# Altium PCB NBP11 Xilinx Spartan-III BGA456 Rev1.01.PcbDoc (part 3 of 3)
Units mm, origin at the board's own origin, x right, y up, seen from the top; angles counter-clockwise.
Board outline 69 x 80.99 mm, 6 copper layers (Top Layer, MidLayer1, InternalPlane1, InternalPlane2, MidLayer2, Bottom Layer); 105 components, 277 nets, 967 pads, 559 vias.
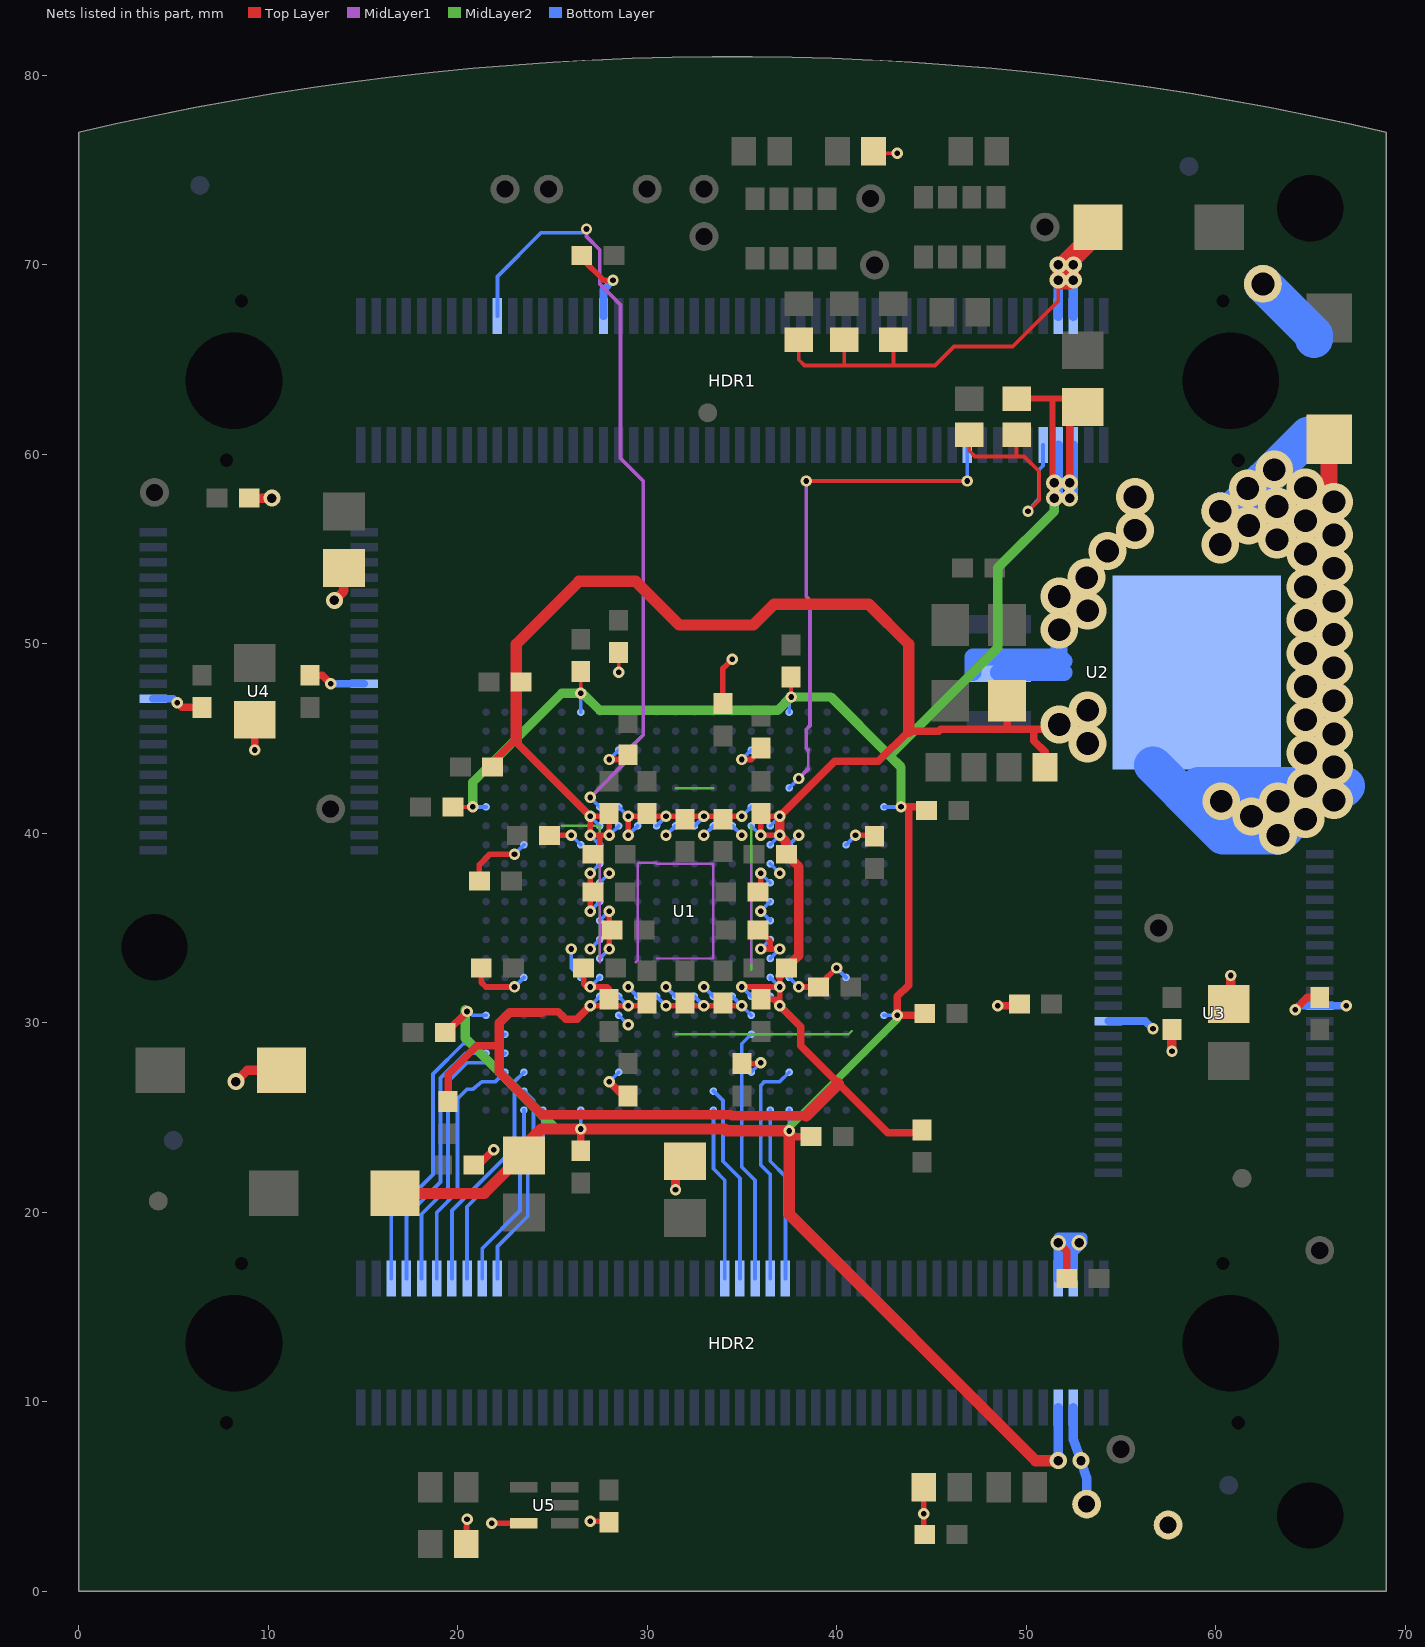
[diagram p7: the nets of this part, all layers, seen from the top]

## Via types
v1: diameter 0.6, hole 0.3, Top Layer to Bottom Layer, tented both sides, 480 vias
v2: diameter 2, hole 1.2, Top Layer to Bottom Layer, tented both sides, 42 vias
v3: diameter 0.9, hole 0.5, Top Layer to Bottom Layer, tented both sides, 33 vias
v4: diameter 0.8, hole 0.5, Top Layer to Bottom Layer, tented both sides, 2 vias
v5: diameter 1.3, hole 0.9, Top Layer to Bottom Layer, tented both sides, 1 vias
v6: diameter 1.8, hole 0.9, Top Layer to Bottom Layer, tented both sides, 1 vias

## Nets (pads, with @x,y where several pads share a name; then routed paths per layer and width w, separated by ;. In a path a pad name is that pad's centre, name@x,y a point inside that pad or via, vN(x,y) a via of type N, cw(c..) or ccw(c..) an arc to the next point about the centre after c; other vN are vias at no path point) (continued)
SW3: HDR2.50 U1.N22 | length 9.1
  Bottom Layer w0.2: U1.N22@33.5,25.4 33.5,22.3 34.1,21.7 HDR2.50@34.1,16.5
SW4: HDR2.52 U1.N21 | length 10.5
  Bottom Layer w0.2: U1.N21@33.5,26.4 34,25.9 34,22.7 34.9,21.8 HDR2.52@34.9,16.5
SW5: HDR2.54 U1.R18 | length 13.4
  Bottom Layer w0.2: U1.R18@35.5,29.4 35,28.9 35,22.4 35.7,21.7 HDR2.54@35.7,16.5
SW6: HDR2.56 U1.U20 | length 12.2
  Bottom Layer w0.2: HDR2.56@36.5,16.5 36.5,22 36,22.5 36,26.7 36.2,26.9 37,26.9 U1.U20@37.5,27.4
SW7: HDR2.58 U1.T22 | length 9.2
  Bottom Layer w0.2: U1.T22@36.5,25.4 36.5,22.7 37.3,21.9 HDR2.58@37.3,16.5
SWC0: HDR2.18 U1.C21 | length 11.2
  Bottom Layer w0.2: HDR2.18@21.3,16.5 21.3,18.1 23.3,20.1 23.3,22.5 24,23.2 24,25.9 U1.C21@23.5,26.4
SWC1: HDR2.16 U1.C22 | length 10.1
  Bottom Layer w0.2: HDR2.16@20.5,16.5 20.5,20.3 23.5,23.3 U1.C22@23.5,25.4
SWC2: HDR2.14 U1.C20 | length 12.5
  Bottom Layer w0.2: HDR2.14@19.7,16.5 19.7,18.1 19.7,20.1 23,23.4 23,26.9 U1.C20@23.5,27.4
SWC3: HDR2.6 U1.B18 | length 16.4
  Bottom Layer w0.2: HDR2.6@16.5,16.5 16.5,19.8 18.7,22 18.7,27.3 20.3,28.9 22,28.9 U1.B18@22.5,29.4
SWR0: HDR2.20 U1.D22 | length 9.9
  Bottom Layer w0.2: HDR2.20@22.1,16.5 22.1,18.2 23.7,19.8 23.7,22.3 24.5,23.1 U1.D22@24.5,25.4
SWR1: HDR2.12 U1.B20 | length 13
  Bottom Layer w0.2: HDR2.12@18.9,16.5 18.9,20 20,21.1 20,26 20.5,26.5 20.8,26.5 21.3,26.9 22,26.9 U1.B20@22.5,27.4
SWR2: HDR2.10 U1.B19 | length 14.6
  Bottom Layer w0.2: HDR2.10@18.1,16.5 18.1,19.9 19.5,21.3 19.5,26.9 20.5,27.9 22,27.9 U1.B19@22.5,28.4
SWR3: HDR2.8 U1.A19 | length 14.3
  Bottom Layer w0.2: HDR2.8@17.3,16.5 17.3,19.8 19.1,21.6 19.1,27.1 20.4,28.4 U1.A19@21.5,28.4
TEST: HDR1.81 U1.U5 | length 27.2
  Top Layer w0.2: v1(38.4,58.6) v1(46.9,58.6)
  MidLayer1 w0.127: 38.5,43.4 38.5,44.4
  MidLayer1 w0.2: v1(38,42.9) 38.5,43.4 ; v1(38.4,58.6) 38.4,52.5 38.6,52.3 38.6,45.7 38.4,45.5 38.4,44.5 38.5,44.4
  Bottom Layer w0.2: U1.U5@37.5,42.4 v1(38,42.9) ; v1(46.9,58.6) HDR1.81@46.9,60.5
VCC: C2.1 C3.1 C9.1 C10.1 C11.1 C12.1 C13.1 C14.1 C15.1 C16.1 C18.2 C35.1 C36.1 C37.1 C38.1 C39.1 C40.1 C41.1 C42.1 C43.1 C44.1 C45.1 C46.1 C47.1 C48.1 C49.1 C50.1 C51.1 C52.1 C53.1 C54.1 C55.1 C56.1 C61.1 C62.1 C63.1 C64.1 HDR1.34 HDR1.94 HDR1.96 HDR2.94 HDR2.96 R1.2 R2.2 R3.2 R4.1 R12.1 R13.2 TP3.1 U1.C8 U1.C15 U1.F8 U1.F15 U1.G9 U1.G10 U1.G11 U1.G12 U1.G13 U1.G14 U1.H3 U1.H6 U1.H17 U1.H20 U1.J7 U1.J16 U1.K7 U1.K16 U1.L7 U1.L16 U1.M7 U1.M16 U1.N7 U1.N16 U1.P7 U1.P16 U1.R3 U1.R6 U1.R17 U1.R20 U1.T9 U1.T10 U1.T11 U1.T12 U1.T13 U1.T14 U1.U8 U1.U15 U1.Y8 U1.Y15 U3.11 U3.33 U4.11 U4.33 U5.5 | length 151.2
  Top Layer w0.2: v1(28.5,48.5) C50.1@28.5,49.55 ; R2.2@38,66.05 38,65 38.3,64.7 40.4,64.7 ; R3.2@40.4,66.05 40.4,64.7 ; R1.2@41.95,76 42.3,75.9 v1(43.2,75.9) ; R4.1@43,66.05 43,64.7 ; v3(51.7,70) v3(51.7,69.2) 51.7,69 51.7,68.1 49.3,65.7 46.2,65.7 45.2,64.7 43,64.7 ; 40.4,64.7 43,64.7
  Top Layer w0.3: R13.2@20.425,2.501 v1(20.5,3.8) ; R13.2@20.45,2.5 R13.2@20.7,2.5 ; C54.1@21.15,37.5 21.15,38.35 21.7,38.9 v1(23,38.9) ; C10.1@21.25,32.9 21.25,32.15 21.5,31.9 v1(23,31.9) ; v1(21.8,3.6) U5.5@23.5,3.6 ; C51.1@24.85,39.9 v1(26,39.9) ; C38.1@26.55,70.498 26.55,70.35 27.7,69.2 v1(28.2,69.2) ; v1(27,3.7) C48.1@28,3.7 ; v1(27,35.9) 27,36.9 v1(27,37.9) ; v1(28,33.9) 28,34.9 v1(28,35.9) ; v1(28,43.9) C15.1@28.9,43.9 ; v1(29,39.9) v1(29,40.9) 30,40.9 v1(31,40.9) 32,40.9 v1(33,40.9) 34,40.9 v1(35,40.9) ; v1(31,30.9) 32,30.9 v1(33,30.9) 34,30.9 v1(35,30.9) ; C9.1@34,46.85 34,48.7 v1(34.5,49.2) ; C49.1@35,27.85 35.95,27.85 v1(36,27.9) ; v1(35,43.9) 35.5,43.9 36,44.4 C11.1@36,44.5 ; C44.1@35.85,34.9 35.9,34.9 36.5,34.3 36.5,33.9 ; C45.1@35.85,36.9 36,37.05 v1(36,37.9) ; v1(36,33.9) 36.5,33.9 ; v1(37,33.9) 36.5,33.9 ; v1(38,31.9) C53.1@39.05,31.9 39.05,31.95 v1(40,32.9) ; v1(41,39.9) C52.1@41.95,39.9 ; C36.1@44.6,3.05 v1(44.6,4.1) R12.1@44.6,5.5
  Top Layer w0.4: v1(5.2,46.9) 5.45,46.65 C35.1@6.5,46.65 ; v1(9.3,44.4) C64.1@9.3,46 ; C12.1@12.2,48.35 12.85,48.35 v1(13.3,47.9) ; C55.1@20.85,22.5 21.1,22.5 v1(21.9,23.3) ; v1(28,26.9) 28.8,26.1 C18.2@29,26.1 ; v1(48.5,30.9) C13.1@49.6,30.9 ; v4(51.7,18.4) 52.15,17.95 C37.1@52.15,16.5 ; v1(64.2,30.7) 64.85,31.35 C47.1@65.5,31.35
  Top Layer w0.5: v3(8.3,26.9) 8.9,27.5 C3.1@10.7,27.5 10.7,27 C3.1@10.8,27 ; C39.1@9.1,57.7 v3(10.2,57.7) ; v3(13.5,52.3) 14,52.8 C61.1@14,54 ; 31.5,21.5 31.5,22.7 C62.1@31.5,22.9 ; v1(57.7,28.5) C46.1@57.7,29.65 ; C63.1@60.8,31 v1(60.8,32.5)
  Top Layer w0.6: v3@52.2,70.1 52.1,70 52.1,69.2 v3@52.1,69 ; C2.1@53.8,71.4 52.5,70.1 v3(52.5,70) v3(52.5,69.2) 52.3,69 v3@52.1,69 ; C2.1@53.8,72 53.7,72 52.1,70.4 v3(51.7,70) v3(51.7,69.2) 51.7,69 v3@52.1,69
  Bottom Layer w0.2: v1(23,31.9) U1.C15@23.5,32.4 ; v1(23,38.9) U1.C8@23.5,39.4 ; v1(26,33.9) 26,32.9 U1.F15@26.5,32.4 ; v1(26,39.9) U1.F8@26.5,39.4 ; v1(27,33.9) U1.G13@27.5,34.4 ; v1(27,35.9) U1.G11@27.5,36.4 ; v1(27,37.9) U1.G9@27.5,38.4 ; U1.G14@27.5,33.4 27.55,33.45 v1(28,33.9) ; U1.G12@27.5,35.4 v1(28,35.9) ; U1.G10@27.5,37.4 v1(28,37.9) ; v1(28,26.9) U1.H20@28.5,27.4 ; v1(28,43.9) U1.H3@28.5,44.4 ; U1.H17@28.5,30.4 v1(29,29.9) ; U1.H6@28.5,41.4 v1(29,40.9) ; v1(29,31.9) U1.J16@29.5,31.4 ; v1(29,39.9) U1.J7@29.5,40.4 ; U1.K16@30.5,31.4 v1(31,30.9) ; U1.K7@30.5,40.4 30.55,40.45 v1(31,40.9) ; v1(31,31.9) U1.L16@31.5,31.4 ; v1(31,39.9) U1.L7@31.5,40.4 ; U1.M16@32.5,31.4 v1(33,30.9) ; U1.M7@32.5,40.4 v1(33,40.9) ; v1(33,31.9) 33.45,31.45 U1.N16@33.5,31.4 ; v1(33,39.9) U1.N7@33.5,40.4 ; U1.P16@34.5,31.4 v1(35,30.9) U1.R17@35.5,30.4 ; U1.P7@34.5,40.4 v1(35,39.9) ; v1(35,40.9) U1.R6@35.5,41.4 ; v1(35,43.9) U1.R3@35.5,44.4 ; U1.R20@35.5,27.4 35.55,27.45 v1(36,27.9) ; v1(36,33.9) U1.T13@36.5,34.4 ; v1(36,37.9) U1.T10@36.5,37.4 ; U1.T14@36.5,33.4 v1(37,33.9) ; U1.T12@36.5,35.5 U1.T12@36.5,35.4 v1(36,35.9) U1.T11@36.5,36.4 ; U1.T9@36.5,38.4 v1(37,37.9) ; U1.U15@37.5,32.4 v1(38,31.9) ; U1.U8@37.5,39.4 37.55,39.45 v1(38,39.9) ; v1(40,32.9) 40.45,32.45 U1.Y15@40.5,32.4 ; U1.Y8@40.5,39.4 40.55,39.45 v1(41,39.9)
  Bottom Layer w0.4: U4.11@3.925,47.1 5,47.1 v1(5.2,46.9) ; v1(13.3,47.9) U4.33@15.075,47.9 ; HDR1.34@27.7,67.3 27.7,68.7 v1(28.2,69.2) ; U3.11@54.35,30.1 56.3,30.1 v1(56.7,29.7) ; v1(64.2,30.7) 64.4,30.9 U3.33@65.5,30.9 ; U3.33@65.3,30.9 U3.33@65.5,30.9 ; 66.375,30.9 v1(66.9,30.9) ; 66.4,30.9 U3.33@65.5,30.9
  Bottom Layer w0.5: HDR2.94@51.7,16.5 51.7,17.9 ; HDR1.94@51.7,67.3 v3(51.7,69.2) v3(51.7,70) ; HDR2.96@52.5,16.5 52.5,17.9 ; HDR1.96@52.5,67.3 v3(52.5,69.2) v3(52.5,70) ; 51.7,17.9 52.3,17.9 52.5,18.1 ; 51.7,17.9 v4(51.7,18.4) ; v4(51.7,18.4) v4(52.8,18.4) 52.5,18.1 ; v4(51.7,18.4) 51.7,18.7 52.8,18.7 53,18.7 53,18.4 52.9,18.3 52.5,17.9 ; 52.5,17.9 52.5,18.1
  other v1: 31.5,21.2
VCCAUX: C1.1 C5.1 C6.1 C19.1 C20.1 C21.1 C22.1 C23.1 C24.1 C58.1 C59.1 HDR1.93 HDR1.95 HDR2.93 HDR2.95 R10.1 TP8.1 U1.A6 U1.A17 U1.AB6 U1.AB17 U1.F1 U1.F22 U1.U1 U1.U22 | length 195
  Top Layer w0.2: C23.1@19.85,41.4 v1(20.8,41.4) ; v1(26.5,47.4) C20.1@26.5,48.55 ; v1(37.6,47.2) C21.1@37.6,48.25 C21.1@37.6,48.3 ; v1(43.4,41.4) 43.8,41.4 C24.1@44.25,41.4
  Top Layer w0.3: R10.1@49.5,62.95 51.4,62.95 ; v3(51.5,58.5) 51.4,58.6 51.4,62.95 ; C59.1@53,63 52.95,62.95 51.4,62.95
  Top Layer w0.4: C22.1@19.395,29.502 19.4,29.4 19.408,29.495 v1(20.5,30.6) ; C19.1@26.5,23.25 v1(26.5,24.4) ; v1(37.5,24.3) 37.8,24 C6.1@38.65,24 ; C5.1@44.55,30.4 v1(43.2,30.4) 43.2,31.4 43.8,32 43.8,41.4 ; C24.1@44.7,41.4 43.8,41.4 ; v3(52.3,58.5) C59.1@52.3,62.1 ; 43.8,41.4 v1(43.4,41.4) 43.8,41.4
  Top Layer w0.6: C1.1@16.7,21 21.4,21 23.4,23 C58.1@23.5,23 23.5,23.5 24.4,24.4 v1(26.5,24.4) 34.1,24.4 34.2,24.3 v1(37.5,24.3) 37.5,19.9 50.5,6.9 v3(51.7,6.9)
  MidLayer2 w0.127: 25.5,40.408 27.484,40.408 ; 27.5,33.408 27.5,40.392 ; 31.5,42.392 33.484,42.392 ; 31.508,29.4 40.627,29.4 40.8,29.572 ; 35.492,40.4 35.492,38.4 35.5,38.392 35.5,32.8
  MidLayer2 w0.4: v1(37.5,24.3) 37.5,24.5 43.2,30.2 v1(43.2,30.4)
  MidLayer2 w0.5: v1@20.4,30.7 20.4,30.6 20.4,29.2 25.2,24.4 v1(26.5,24.4) ; v1(20.8,41.4) 20.8,42.7 25.5,47.4 v1(26.5,47.4) 26.6,47.4 27.5,46.5 36.9,46.5 v1(37.6,47.2) 39.7,47.2 42.8,44.1 ; v1(43.4,41.4) 43.4,43.5 42.8,44.1 ; v3(51.5,57.7) 51.5,57 48.5,54 48.5,49.8 42.8,44.1
  Bottom Layer w0.2: v1(20.5,30.6) 20.8,30.4 U1.A17@21.5,30.4 ; v1(20.8,41.4) U1.A6@21.5,41.4 ; v1(26.5,24.4) U1.F22@26.5,25.4 ; U1.F1@26.5,46.4 v1(26.5,47.4) ; v1@37.5,24.5 U1.U22@37.5,25.4 ; U1.U1@37.5,46.4 37.5,47.1 v1(37.6,47.2) ; U1.AB17@42.5,30.4 v1(43.2,30.4) ; U1.AB6@42.5,41.4 v1(43.4,41.4)
  Bottom Layer w0.5: v3(51.5,57.7) 51.7,57.9 51.7,58.5 HDR1.93@51.7,60.5 ; v3(51.7,6.9) HDR2.93@51.7,9.7 ; v3(52.3,57.7) 52.5,57.9 52.5,58.5 HDR1.95@52.5,60.5 ; HDR2.95@52.5,9.7 52.5,8 v3(52.9,6.9) ; v3@52.734,6.866 v3(52.9,6.9) ; TP8.1@53.2,4.6 53.2,6 v3(52.9,6.9)
VCCINT: C4.1 C7.1 C8.1 C25.1 C26.1 C27.1 C28.1 C29.1 C30.1 C31.1 C32.1 C33.1 C34.1 C57.1 C60.1 R14.1 TP16.1 U1.G7 U1.G8 U1.G15 U1.G16 U1.H7 U1.H16 U1.R7 U1.R16 U1.T7 U1.T8 U1.T15 U1.T16 U2.2 U2.4 | length 222.7
  Top Layer w0.3: C29.1@26.65,32.9 26.65,32.05 26.8,31.9 v1(27,31.9) 27.9,31.9 28,31.8 C57.1@28,31.25 ; v1(27,30.9) 28,30.9 v1(29,30.9) 30,30.9 C34.1@30.1,30.9 ; C33.1@27.5,38.8 27.5,38.9 27.5,39.9 ; v1(35,31.9) 36,31.9 v1(37,31.9) ; C25.1@36,31.25 36.65,31.25 ; C31.1@37,32.5 v1(37,31.9) ; v1(37,39.9) v1(36,39.9) 36,40.75 36.15,40.9 v1(37,40.9) ; 27.5,39.9 v1(28,39.9) C28.1@28,41.05 27.85,40.9 v1(27,40.9) v1(27,39.9) 27.5,39.9 ; 36.65,31.25 36.95,31.25 37,31.3 ; 36.65,31.25 v1(37,30.9) 37,31.3 ; 37,31.3 v1(37,31.9)
  Top Layer w0.4: C27.1@19.5,25.85 19.5,27.3 21,28.8 22.2,28.8 22.2,30 ; C8.1@21.8,43.7 23,44.9 23.1,44.9 23.1,44.8 v1(27,40.9) ; 24.449,30.6 25.3,30.6 25.7,30.2 26.3,30.2 v1(27,30.9) ; v1(37,30.9) 38.1,29.8 38.1,28.8 40.109,26.791 ; v1(37,40.9) 39.9,43.8 42.2,43.8 43.8,45.4 45.4,45.4 45.5,45.5 50.4,45.5 ; 40.091,26.791 40.109,26.791 ; C26.1@44.3,24.2 42.7,24.2 40.109,26.791 ; 49,45.5 C60.1@49,47 ; R14.1@51,43.5 51,44.3 50.4,44.9 50.4,45.5 ; v2(51.75,45.75) 51.5,45.5 50.4,45.5
  Top Layer w0.5: 24.449,30.549 22.749,30.549 22.2,30 22.2,28.8 22.2,27.4 24.45,25.15 34.411,25.15 34.461,25.1 38.4,25.1 ; C31.1@37,32.5 C31.1@37.35,32.9 38,33.55 38,38.25 C30.1@37.35,38.9 37.323,38.927 37.323,39.577 v1(37,39.9) v1(37,40.9)
  Top Layer w0.6: 23.1,44.9 23.1,48 23.1,50 26.4,53.3 29.4,53.3 31.7,51 35.6,51 36.7,52.1 41.7,52.1 43.8,50 43.8,45.4 ; 38.4,25.1 40.091,26.791
  Top Layer w0.9: v2(64.75,56.5) 65.625,57.375 66,57.75 66,58.25 C4.1@66,60.8
  MidLayer1 w0.127: 27.5,33.2 27.5,38.392 ; 29.4,33.2 29.5,33.3 29.5,38.392 ; 29.564,38.45 30.45,38.45 30.508,38.392 33.5,38.392 33.492,38.384 33.492,33.4 30.508,33.4 ; 35.5,33.2 35.5,38.392
  Bottom Layer w0.2: v1(27,30.9) U1.G16@27.5,31.4 ; v1(27,31.9) U1.G15@27.5,32.4 ; v1(27,39.9) 27.45,39.45 U1.G8@27.5,39.4 ; v1(27,40.9) U1.G7@27.5,40.4 ; v1(28,39.9) U1.H7@28.5,40.4 ; U1.H16@28.5,31.4 v1(29,30.9) ; v1(35,31.9) 35.45,31.45 U1.R16@35.5,31.4 ; U1.R7@35.5,40.4 v1(36,39.9) ; U1.T16@36.5,31.4 v1(37,30.9) ; U1.T15@36.5,32.3 U1.T15@36.5,32.4 v1(37,31.9) ; U1.T8@36.5,39.4 v1(37,39.9) ; U1.T7@36.5,40.4 36.55,40.45 v1(37,40.9)
  Bottom Layer w0.9: U2.2@47.2,48.5 47.2,49.3 ; 47.4,49.1 47.2,49.3 ; U2.2@48.55,48.5 52,48.5 ; 51.75,49.1 52,49.1 51.75,49.35 ; v2(51.75,50.75) 51.75,49.35 ; v2@62.972,58.183 63,58 v2@63,57.8 ; 47.2,49.3 48.55,49.3 51.7,49.3 51.75,49.35
  Bottom Layer w2: U2.4@56.7,43.6 59.45,40.85 60.4,39.9 61.9,39.9 v2(63.3,39.9) 64.2,40.8 64.45,41.05 65.325,41.925 65.7,42.3 65.8,42.4 66.25,42.4 66.8,42.4 66.9,42.5 66.25,42.5 v2(64.75,42.5) 63.3,42.5 61.9,42.5 60.3,42.5 59.1,42.5 59.9,41.7 v2(60.3,41.7) 61.9,41.7 v2(63.3,41.7) ; v2(60.25,57) 60.9,57 60.95,57.05 61.9,58 62.2,58.3 v2(63.1,59.2) 63.45,59.55 64.9,61 ; TP16.1@62.5,69 65.2,66.3 65.2,66.1
  other v2: 64.75,40.75 61.9,40.9 66.25,41.75 66.25,43.5 64.75,44.25 53.25,44.75 66.25,45.25 64.75,46 53.25,46.5 66.25,47 64.75,47.75 66.25,48.75 64.75,49.5 66.25,50.5 64.75,51.25 53.25,51.75 66.25,52.25 51.75,52.5 64.75,53 53.2,53.5 66.25,54 64.75,54.75 54.3,54.9 60.25,55.25 63.25,55.5 66.25,55.75 55.75,56 61.75,56.25 63.25,57.25 66.25,57.5 55.75,57.75 61.7,58.2 64.75,58.25
VDRIVE: HDR1.20 U1.G6 | length 40.9
  MidLayer1 w0.2: v1(26.8,71.9) 26.8,71.5 27.5,70.8 27.5,69 28.6,67.9 28.6,59.8 29.8,58.6 29.8,45.2 29,44.4 29,43.9 v1(27,41.9)
  Bottom Layer w0.2: HDR1.20@22.1,67.3 22.1,69.4 24.4,71.7 26.6,71.7 v1(26.8,71.9) ; v1(27,41.9) U1.G6@27.5,41.4
VREF: HDR1.91 R10.2 R11.1 | length 12.3
  Top Layer w0.2: R11.1@47,61.05 47,60.2 47.3,59.9 49.5,59.9 ; R10.2@49.5,61.05 49.5,59.9 ; v1(50.1,57) 50.7,57.6 50.7,59.1 49.9,59.9 49.5,59.9
  Bottom Layer w0.2: v1(50.1,57) 50.7,57.7 50.7,59.2 50.9,59.4 HDR1.91@50.9,60.5
pads on no net: HDR1.MH1 HDR1.MH2 HDR1.MH3 HDR1.MH4 HDR1.MH5 HDR1.MH6 HDR2.MH1 HDR2.MH2 HDR2.MH3 HDR2.MH4 HDR2.MH5 HDR2.MH6 U1.A7 U1.A16 U1.AA3 U1.AA7 U1.AA9 U1.AA11 U1.AA12 U1.AA16 U1.AA19 U1.AB7 U1.AB9 U1.AB14 U1.AB16 U1.AB19 U1.B7 U1.B11 U1.B16 U1.C16 U1.D8 U1.D16 U1.E5 U1.E8 U1.F6 U1.F14 U1.G3 U1.G4 U1.G5 U1.G20 U1.H1 U1.H2 U1.H4 U1.H18 U1.H19 U1.H21 U1.H22 U1.J1 U1.J2 U1.J4 U1.J5 U1.J6 U1.J17 U1.J18 U1.J19 U1.J21 U1.J22 U1.K5 U1.K6 U1.K17 U1.K18 U1.N5 U1.N6 U1.N17 U1.N18 U1.P1 U1.P2 U1.P4 U1.P5 U1.P6 U1.P17 U1.P18 U1.P19 U1.P21 U1.P22 U1.R1 U1.R2 U1.R4 U1.R5 U1.R19 U1.R21 U1.R22 U1.T3 U1.T17 U1.T19 U1.T20 U1.U9 U1.U12 U1.U14 U1.V11 U1.V12 U1.V15 U1.W3 U1.W7 U1.W11 U1.W15 U1.Y4 U1.Y7 U1.Y11 U1.Y12 U5.1

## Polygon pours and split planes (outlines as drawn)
VCCAUX on Top Layer "Top Layer-VCCAUX" (solid, remove dead copper, pour order 1001): 72.278,82.178 72.31,82.1 72.31,-2.3 72.278,-2.378 72.2,-2.41 -2.7,-2.41 -2.778,-2.378 -2.81,-2.3 -2.81,81.899 -3.909,81.99 -3.943,82.008 -3.978,82.022 -3.98,82.027 -3.984,82.029 -3.995,82.065 -4.01,82.1 -4.008,82.104 -4.01,82.109 -3.992,82.143 -3.978,82.178 -3.973,82.18 -3.971,82.184 -3.935,82.195 -3.9,82.21 72.2,82.21
VCCINT on Top Layer "Top Layer-VCCINT" (solid, remove dead copper, pour order 1000): 43.7,81.51 43.701,81.51 70.2,81.31 74.4,81.31 74.478,81.278 74.51,81.2 74.51,-4.1 74.478,-4.178 74.4,-4.21 52.4,-4.21 52.322,-4.178 52.29,-4.1 52.29,11.754 39.654,24.39 17.2,24.39 17.122,24.422 12.822,28.722 12.79,28.8 12.79,34.3 12.822,34.378 15.79,37.346 15.79,45.3 15.822,45.378 17.422,46.978 24.422,53.978 24.5,54.01 43.054,54.01 44.822,55.778 44.9,55.81 53.154,55.81 53.99,56.646 53.99,70.954 43.622,81.322 43.622,81.323 43.606,81.361 43.59,81.4 43.59,81.401 43.606,81.439 43.622,81.478 43.623,81.478 43.661,81.494 43.7,81.51
GND on MidLayer1 "MidLayer1-GND" (solid, remove dead copper, pour order 1004): 72.478,83.678 72.51,83.6 72.51,-3 72.478,-3.078 72.4,-3.11 -4.6,-3.11 -4.639,-3.094 -4.678,-3.078 -4.694,-3.039 -4.71,-3 -4.91,83.6 -4.894,83.639 -4.878,83.678 -4.839,83.694 -4.8,83.71 72.4,83.71
VCCINT on MidLayer1 "MidLayer1-VCCINT 1" (solid, remove dead copper, pour order 1003): 45.478,48.678 45.51,48.6 45.51,22.6 45.478,22.522 45.4,22.49 18.6,22.49 18.522,22.522 18.49,22.6 18.49,48.6 18.522,48.678 18.6,48.71 45.4,48.71
VCCINT on MidLayer1 "MidLayer1-VCCINT" (solid, remove dead copper, pour order 1002): 43.401,84.41 72.601,84.11 72.639,84.094 72.678,84.078 72.678,84.077 72.679,84.077 72.694,84.038 72.71,84 72.71,33.5 72.678,33.422 72.6,33.39 43.4,33.39 43.322,33.422 43.29,33.5 43.29,84.3 43.29,84.301 43.306,84.339 43.322,84.378 43.323,84.378 43.323,84.379 43.362,84.394 43.4,84.41
VCCAUX on MidLayer2 "MidLayer2-VCCAUX" (solid, remove dead copper, pour order 1006): -7.4,84.61 -7.399,84.61 60.001,84.21 60.039,84.194 60.078,84.178 60.078,84.177 60.094,84.139 60.11,84.1 60.11,-10.9 60.078,-10.978 60,-11.01 -7.4,-11.01 -7.478,-10.978 -7.51,-10.9 -7.51,84.5 -7.51,84.501 -7.494,84.539 -7.478,84.578 -7.477,84.578 -7.439,84.594 -7.4,84.61
VCCINT on MidLayer2 "MidLayer2-VCCINT" (solid, remove dead copper, pour order 1005): 72.436,84.795 72.474,84.782 72.475,84.779 72.478,84.778 72.493,84.741 72.51,84.706 72.509,84.703 72.51,84.7 72.51,-4.1 72.478,-4.178 72.4,-4.21 57.3,-4.21 57.222,-4.178 57.19,-4.1 57.19,25.454 47.622,35.022 47.59,35.1 47.59,44.7 47.622,44.778 50.09,47.246 50.09,53.1 50.122,53.178 53.79,56.846 53.79,59.89 42.8,59.89 42.722,59.922 42.69,60 42.69,83.2 42.705,83.236 42.718,83.274 42.721,83.275 42.722,83.278 42.759,83.293 42.794,83.31 72.394,84.81 72.397,84.809 72.4,84.81
+5 on Bottom Layer "Bottom Layer-+5" (solid, remove dead copper, pour order 1009): 56.478,62.778 56.51,62.7 56.51,49 56.478,48.922 56.4,48.89 43,48.89 42.922,48.922 42.89,49 42.89,62.7 42.922,62.778 43,62.81 56.4,62.81
GND on Bottom Layer "Bottom Layer-GND" (solid, remove dead copper, pour order 1008): 43.578,83.878 43.61,83.8 43.61,47.8 43.578,47.722 43.5,47.69 19.71,47.69 19.71,23.31 43.19,23.31 43.19,44.6 43.204,44.633 43.213,44.667 43.219,44.671 43.222,44.678 43.255,44.691 43.286,44.709 43.293,44.707 43.3,44.71 43.333,44.696 43.367,44.687 43.371,44.681 43.378,44.678 43.391,44.645 43.409,44.614 43.566,43.379 69.8,43.379 69.878,43.346 69.91,43.269 69.91,-3.5 69.878,-3.578 69.8,-3.61 -2.5,-3.61 -2.578,-3.578 -2.61,-3.5 -2.61,81.2 -2.578,81.278 0.022,83.878 0.1,83.91 43.5,83.91
VCCINT on Bottom Layer "Bottom Layer-VCCINT" (solid, remove dead copper, pour order 1007): 72.578,83.178 72.61,83.1 72.61,31 72.578,30.922 72.5,30.89 42.5,30.89 42.461,30.906 42.422,30.922 42.406,30.961 42.39,31 42.49,83.1 42.506,83.139 42.522,83.178 42.561,83.194 42.6,83.21 72.5,83.21
VCC on InternalPlane1 (split plane): 36.232,80.189 37.965,80.159 39.696,80.109 41.427,80.039 43.158,79.949 44.887,79.839 46.614,79.709 48.34,79.559 50.064,79.389 51.786,79.2 53.506,78.99 55.223,78.761 56.938,78.511 58.649,78.242 60.358,77.953 62.062,77.645 63.763,77.317 65.461,76.969 67.154,76.602 68.197,76.363 68.197,0.803 0.803,0.803 0.803,76.363 1.846,76.602 3.539,76.969 5.237,77.317 6.938,77.645 8.642,77.953 10.351,78.242 12.062,78.511 13.777,78.761 15.494,78.99 17.214,79.2 18.936,79.389 20.66,79.559 22.386,79.709 24.113,79.839 25.842,79.949 27.573,80.039 29.304,80.109 31.035,80.159 32.768,80.189 34.5,80.199
GND on InternalPlane2 (split plane): 36.232,80.189 37.965,80.159 39.696,80.109 41.427,80.039 43.158,79.949 44.887,79.839 46.614,79.709 48.34,79.559 50.064,79.389 51.786,79.2 53.506,78.99 55.223,78.761 56.938,78.511 58.649,78.242 60.358,77.953 62.062,77.645 63.763,77.317 65.461,76.969 67.154,76.602 68.197,76.363 68.197,0.803 0.803,0.803 0.803,76.363 1.846,76.602 3.539,76.969 5.237,77.317 6.938,77.645 8.642,77.953 10.351,78.242 12.062,78.511 13.777,78.761 15.494,78.99 17.214,79.2 18.936,79.389 20.66,79.559 22.386,79.709 24.113,79.839 25.842,79.949 27.573,80.039 29.304,80.109 31.035,80.159 32.768,80.189 34.5,80.199

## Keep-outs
Top Layer:
  circle w0.254: c61.4,21.8 r2.5
  circle w0.254: c33.2,62.2 r2.5
  circle w0.254: c4.2,20.6 r2.5
Bottom Layer:
  circle w0.254: c60.7,5.6 r2.5
  circle w0.254: c6.4,74.2 r2.5
  circle w0.254: c58.6,75.2 r2.5
  circle w0.254: c5,23.8 r2.5
Keep-Out Layer:
  the board outline again, w1.8

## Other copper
Top Layer:
  rectangle net VCCAUX: 51.4,57.4 52.6,62.95
Bottom Layer:
  rectangle net VCCINT: 63.9,57.3 67.9,68.3
  rectangle net VCCAUX: 51,57.2 52.8,59
  rectangle net VCCAUX: 51.5,57.3 52.7,59.5
  rectangle net GND: 53.3,68.6 55.1,70.5
  rectangle net VCC: 51.2,68.6 53,70.5
  rectangle net VCCINT: 55,42.5 67.9,58.5
  rectangle net VCCINT: 53.6,42.5 59.7,55.4
  rectangle net VCCINT: 51.3,42.5 61.5,53.3
  rectangle net VCCAUX: 51.5,6.5 52.7,8.6

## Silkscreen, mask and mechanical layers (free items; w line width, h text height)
Top Overlay:
  circle w0.127: c65,73 r2.5
  circle w0.127: c65,4 r2.5
  circle w0.127: c4,34 r2.5
  lines w0.08: 6,72.8 6.2,73 8.4,73 ; 8.4,58.45 8.6,58.8 11.2,58.8 ; 9.9,54.7 12.4,54.7 ; 17.1,35.3 19.7,35.3 20.2,35.8 22.4,35.8 23.4,35.4 27.2,35.4 27.4,35.2 ; 17.2,38.5 25,38.5 26.5,36.9 ; 17.5,25.8 18.6,25.8 ; 17.513,42.12 17.9,42.1 ; 17.72,75.22 21.6,74 ; 19.713,44.22 20.15,44.25 ; 20,29 22.4,29 ; 20.1,37.1 21,36.7 ; 20.7,39.3 22.6,39.2 ; 22.513,34.62 23.2,34.4 26.2,34.4 26.6,33.9 ; 23.6,51.6 25.5,51.6 25.8,50.6 ; 23.6,69.8 26.498,69.8 26.55,69.748 ; 23.82,75.22 24.2,74.6 ; 24.7,45.5 22.6,45.5 27.6,39.8 ; 25.2,30.4 27,30.3 ; 25.4,25.2 28,25.2 28.2,25.8 ; 27.3,21.3 27.5,19.9 ; 27.4,45.5 27.5,43.6 ; 28,75.1 29.2,74.4 ; 29.4,51.4 29.6,51.7 31.9,51.7 ; 29.75,45.85 29.9,46.4 ; 30,25.3 32.4,25.3 32.5,30.4 ; 30,30.5 30.2,30.1 ; 30.5,48 32.6,48 32.3,41.5 ; 30.6,43.5 30.7,45.3 ; 30.8,78.2 32.9,74.8 ; 30.9,24.1 33.3,24.1 33.6,30.3 ; 32.8,68.7 33,70.7 ; 33.2,47.2 33.4,47.6 ; 34.5,41.2 34.5,43.4 ; 36.6,34.5 38.1,34.5 ; 36.6,37.1 36.8,37.3 39.3,37.3 40,36.6 ; 36.7,50.3 36.72,51.92 ; 36.75,45.3 38.1,45.3 ; 37,29.6 40.52,29.32 ; 37,42.3 38.7,42.3 ; 37.15,77 37.62,77.22 ; 38,38.8 38.4,38.8 41,41.4 ; 38.1,33.3 39,33.3 40.1,34.6 ; 40.2,71.6 41.789,71.6 ; 40.2,77.5 40.6,77 ; 40.9,61.6 45.1,61.6 45.2,61.6 44.6,68.2 42.5,69.5 ; 41.2,32.6 41.72,33.02 ; 42,43 44.4,43 ; 42.2,50.5 44.2,50.5 45.1,49.6 ; 42.2,70.8 43.884,70.8 ; 42.4,77.4 45.1,77.4 42.6,74.2 ; 42.5,45.9 44.5,45.9 45.4,45.5 ; 42.75,38.3 45.2,38.3 ; 46.1,63.4 46.1,64 ; 48.3,67 48.4,66.9 49.9,66.9 ; 48.5,63.5 48.5,64 ; 50.4,74.4 50.9,72.9 ; 51.4,42.6 51.5,42.5 54.1,42.5 ; 54.5,30.1 56.85,30.1 56.95,30.2 ; 55.8,7.2 55.9,7.1 58.7,7.1 ; 55.8,74.4 55.82,75.12 ; 57.9,2.6 58.8,1.7 61.5,1.7 ; 57.9,35 61.2,35 ; 59.5,68.8 61.3,69 ; 65.5,32 65.5,32.3
  lines w0.127: 0,1.5 1.5,1.5 1.5,0 ; 0,22.3 1.5,22.3 1.5,23.4 0,23.4 ; 0.001,53.6 1.501,53.6 1.501,54.7 0.001,54.7 ; 0,75.5 1.5,75.5 1.5,77.3 ; 15.7,79.8 15.7,78.1 17,78.1 17,79.9 ; 49.7,80.2 49.7,78.7 51,78.7 51,80.1 ; 67.5,0 67.5,1.5 69,1.5 ; 67.5,77.3 67.5,75.5 69,75.5 ; 68.999,22.3 67.5,22.3 67.5,23.4 69,23.4 ; 69,53.6 67.501,53.6 67.501,54.7 69.001,54.7
  text "GND" at 6.2,73.3 h0.8
Bottom Overlay:
  drawing of 856 lines, arcs and shapes, not listed
  text "NBP11" at 54.5,76.5 h1.3
  text "REV 1.01" at 47.7,76.4 h1.3
  text "1" at 14.4,58.4 h1
  text "1" at 14.224,7.62 h1
PCB Boundary:
  the board outline again, w0.25
  text "PCB boundary coincides with centre-line of tracks and arc" at 0,-12 h0.75
Gerber ID:
  text ".Layer_Name" at 0,-6 h0.75
Printout ID:
  text ".Printout_Name" at 0,-10 h0.75
Design Information:
  drawing of 719 lines, arcs and shapes, not listed
  text "NBP11 REV 1.01" at 317.627,202.041 h1.27
  text "DESIGN INFORMATION" at 261.62,201.914 h1.52
  text "BOARD NAME:" at 299.212,201.914 h1.52
  text "BOARD TECHNOLOGY" at 261.62,199.374 h1.52
  text "BOARD SIZE (REFER ALSO PROFILING INFORMATION)" at 309.88,199.374 h1.27
  text "69.00mm" at 312.6,197.1 h1.52
  text "15.748" at 277.419,197.012 h1.52
  text "81.00mm" at 335.6,197 h1.52
  text "5.000" at 291.389,196.885 h1.52
  text "5" at 266.446,196.834 h1.52
  text "X" at 328.549,196.326 h1.78
  text "(MIN. TRACK/   PADS  /   CLEARANCE     IN 0.001'')" at 260.096,194.294 h1.27
  text "MINIMUM ANNULAR RING 0.05MM (0.002'') EXTERNAL PER IPC-2221 CLASS 3 LEVEL C AND IS THE" at 261.62,191.754 h1.27
  text "MANUFACTURING REGISTRATION ALLOWANCE" at 261.62,189.468 h1.27
  text "LAND SIZE CALCULATION MINIMUM - NOMINAL HOLE SIZE + 0.508MM (0.020'')" at 261.62,186.674 h1.27
  text "AS INSTRUCTED" at 347.65,182.28 h1.52
  text "X" at 299.263,182.153 h1.52
  text "CIRCUIT TYPE:" at 261.62,182.102 h1.52
  text "SS" at 284.48,182.102 h1.27
  text "DS" at 302.26,182.102 h1.27
  text "X" at 316.865,182.102 h1.52
  text "PTH" at 320.04,182.102 h1.27
  text "ML" at 330.962,182.102 h1.27
  text "X" at 334.772,182.102 h1.52
  text "No. OFF" at 337.82,182.102 h1.27
  text "FINGER CONNECTOR DIM PER:" at 261.62,179.054 h1.52
  text "AS SHOWN" at 337.82,179.054 h1.27
  text "No. OFF TOTAL" at 278.384,176.26 h1.52
  text "ONE SIDE" at 320.04,176.26 h1.27
  text "BOTH SIDES" at 337.82,176.006 h1.27
  text "VIAS:" at 261.62,173.339 h1.52
  text "NONE" at 273.05,173.339 h1.14
  text "X" at 281.432,173.339 h1.52
  text "FEED THRU'" at 284.48,173.339 h1.14
  text "X" at 299.212,173.339 h1.52
  text "TENTED" at 302.26,173.339 h1.14
  text "BURIED LAYER SEQUENCE" at 320.04,173.339 h1.14
  text "UNIQUE DRILL" at 284.48,170.291 h1.14
  text "2 SIZE" at 302.26,170.291 h1.14
  text "BLIND LAYER SEQUENCE" at 320.04,170.291 h1.14
  text "Layer Stack Manager (Protel)" at 297.053,168.005 h1.27
  text "X" at 334.772,168.005 h1.52
  text "AS SHOWN" at 337.82,168.005 h1.27
  text "LAYER CONSTRUCTION PER:" at 261.62,167.878 h1.52
  text "Protel" at 342.646,165.338 h1.27
  text "(PFW)" at 352.933,165.211 h1.27
  text "ARTWORK:" at 261.62,165.084 h1.52
  text "MANUAL" at 284.48,165.084 h1.27
  text "DIGITISED" at 302.26,165.084 h1.27
  text "X" at 316.992,165.084 h1.52
  text "CAD" at 320.04,165.084 h1.27
  text "TYPE" at 330.962,165.084 h1.27
  text "ARTWORK/PATTERN MASTER LIST" at 261.62,160.385 h1.52
  text "DESCRIPTION" at 262.89,157.972 h1.27
  text "DRAWING No./CAD FILE REF." at 281.559,157.972 h1.27
  text "LAYER NAME" at 322.834,157.972 h1.27
  text "GERBER FILE REF" at 343.586,157.896 h1.27
  text "PCB FILE" at 261.366,155.432 h1.27
  text "SpartanIIIBGA456" at 281.737,155.356 h1.27
  text "PcbDoc" at 312.979,155.356 h1.02
  text "Top Paste Mask" at 321.158,152.892 h1.02
  text "GTP" at 363.779,152.816 h1.27
  text "GERBER FILE" at 261.366,152.765 h1.27
  text "GTO" at 363.728,150.327 h1.27
  text "Top Overlay" at 321.158,150.301 h1.02
  text "GERBER FILE" at 261.366,150.225 h1.27
  text "Top Solder Mask" at 321.158,147.863 h1.02
  text "GTS" at 363.779,147.736 h1.27
  text "GERBER FILE" at 261.366,147.685 h1.27
  text "TOP LAYER" at 321.158,145.272 h1.02
  text "GTL" at 363.779,145.196 h1.27
  text "GERBER FILE" at 261.366,145.145 h1.27
  text "G1" at 363.728,142.834 h1.27
  text "MIDLAYER1" at 321.158,142.732 h1.02
  text "GERBER FILE" at 261.366,142.605 h1.27
  text "INTERNALPLANE1" at 321.158,140.192 h1.02
  text "GP1" at 363.779,140.116 h1.27
  text "GERBER FILE" at 261.366,140.065 h1.27
  text "INTERNALPLANE2" at 321.158,137.652 h1.02
  text "GP2" at 363.728,137.627 h1.27
  text "GERBER FILE" at 261.366,137.525 h1.27
  text "MIDLAYER2" at 321.158,135.112 h1.02
  text "G2" at 363.728,135.087 h1.27
  text "GERBER FILE" at 261.366,134.985 h1.27
  text "BOTTOMLAYER" at 321.158,132.572 h1.02
  text "GBL" at 363.779,132.496 h1.27
  text "GERBER FILE" at 261.366,132.445 h1.27
  text "Bottom Solder Mask" at 321.158,130.083 h1.02
  text "GBS" at 363.779,129.956 h1.27
  text "GERBER FILE" at 261.366,129.905 h1.27
  text "Bottom Overlay" at 321.158,127.492 h1.02
  text "GBO" at 363.779,127.416 h1.27
  text "GERBER FILE" at 261.366,127.365 h1.27
  text "Bottom Paste Mask" at 321.158,125.003 h1.02
  text "GBP" at 363.779,124.876 h1.27
  text "GERBER FILE" at 261.366,124.825 h1.27
  text "PCB Boundary" at 321.158,122.412 h1.02
  text "GM1" at 363.779,122.336 h1.27
  text "GERBER FILE" at 261.366,122.285 h1.27
  text "APERTURE LIST" at 261.366,119.872 h1.27
  text "APR" at 313.979,119.796 h1.27
  text "DRILL REPORT" at 261.366,117.332 h1.27
  text "DRR" at 313.979,117.256 h1.27
  text "EXCELLON DRILL" at 261.366,114.792 h1.27
  text "TXT" at 313.979,114.716 h1.27
  text "MATERIAL:" at 261.62,99.298 h1.52
  text "GLASS FIBRE EPOXY RESIN NEMA GRADE FR4 (MIL-S-13949H)" at 287.274,99.044 h1.27
  text "X" at 284.607,98.917 h1.52
  text "THICKNESS:" at 269.494,96.123 h1.27
  text "0.8mm" at 287.274,96.123 h1.27
  text "1.2mm" at 304.927,96.123 h1.27
  text "1.6mm" at 322.58,96.123 h1.27
  text "2.4mm" at 340.36,96.123 h1.27
  text "3.2mm" at 358.14,96.123 h1.27
  text "X" at 320.167,95.996 h1.52
  text "TOLERANCE:" at 269.367,93.075 h1.27
  text "IN A/W IPC-D-300G CLASS" at 287.02,93.075 h1.27
  text "3 LEVEL B" at 321.945,93.075 h1.27
  text "OTHER +/-" at 340.36,93.075 h1.27
  text "X" at 284.607,92.948 h1.52
  text "BOW & TWIST:" at 266.954,90.027 h1.27
  text "IN A/W IPC-D-300G CLASS" at 287.02,90.027 h1.27
  text "3 LEVEL B" at 321.945,90.027 h1.27
  text "AS SHOWN" at 340.487,89.9 h1.27
  text "X" at 284.607,89.773 h1.52
  text "COPPER THICKNESS (FINISHED)" at 269.367,86.725 h1.27
  text "OUTER:" at 274.193,84.439 h1.27
  text "18um" at 287.274,84.439 h1.27
  text "35um" at 314.325,84.439 h1.27
  text "70um" at 340.614,84.439 h1.27
  text "X" at 311.582,84.236 h1.52
  text "INNER SIGNAL:" at 265.811,81.391 h1.27
  text "18um" at 287.274,81.391 h1.27
  text "35um" at 314.325,81.391 h1.27
  text "70um" at 340.614,81.391 h1.27
  text "X" at 311.531,81.188 h1.52
  text "INNER PWR:" at 269.494,78.343 h1.27
  text "18um" at 287.274,78.343 h1.27
  text "35um" at 314.325,78.343 h1.27
  text "70um" at 340.614,78.343 h1.27
  text "X" at 311.658,78.216 h1.52
  text "STRUCTURE:" at 261.62,75.295 h1.52
  text "REFER" at 287.274,75.295 h1.27
  text "AS PER DRAWING No." at 287.147,72.12 h1.27
  text "AS SHOWN" at 340.487,72.12 h1.27
  text "X" at 337.947,71.993 h1.52
  text "DRILLING:" at 261.62,69.326 h1.52
  text "VIEWED FROM:" at 266.573,67.04 h1.27
  text "COMPONENT SIDE" at 287.274,67.04 h1.14
  text "SOLDER SIDE" at 314.071,67.04 h1.14
  text "X" at 284.607,66.786 h1.52
  text "REFERENCE:" at 268.859,63.992 h1.27
  text "AS SHOWN" at 287.147,63.865 h1.14
  text "PATTERN MASTER LIST" at 314.198,63.865 h1.14
  text "X" at 337.947,63.865 h1.52
  text "NC_DRILL FILES" at 340.487,63.865 h1.14
  text "X" at 284.607,63.738 h1.52
  text "PTH MINIMUM COPPER THICKNESS:" at 274.701,60.944 h1.27
  text "20um" at 314.325,60.944 h1.27
  text "X" at 311.658,60.817 h1.52
  text "OTHER" at 340.487,60.817 h1.27
  text "NPTH:" at 275.209,57.896 h1.27
  text "TENTED" at 287.147,57.769 h1.14
  text "X" at 311.658,57.769 h1.52
  text "PADS REMOVED" at 314.198,57.769 h1.14
  text "REMOVE PADS" at 340.487,57.769 h1.14
  text "X" at 284.607,57.642 h1.52
  text "2nd DRILL" at 287.147,54.721 h1.14
  text "BOTH" at 314.198,54.721 h1.14
  text "AS SHOWN" at 326.517,54.721 h1.14
  text "NONE" at 340.487,54.721 h1.14
  text "BOARD FINISH:" at 261.62,51.8 h1.52
  text "X" at 284.607,51.673 h1.52
  text "ETCHING" at 287.147,51.673 h1.14
  text "REFER PATTERN MASTER LIST" at 314.198,51.673 h1.14
  text "LEGEND / SCREEN PRINT:" at 281.94,48.752 h1.27
  text "NONE" at 314.198,48.625 h1.14
  text "COMPONENT" at 326.517,48.625 h1.14
  text "SOLDER" at 340.487,48.625 h1.14
  text "X" at 323.977,48.498 h1.52
  text "X" at 337.947,48.498 h1.52
  text "COLOUR:" at 272.161,45.704 h1.27
  text "WHITE" at 287.147,45.577 h1.14
  text "YELLOW" at 314.198,45.577 h1.14
  text "OTHER" at 340.487,45.577 h1.14
  text "X" at 284.607,45.45 h1.52
  text "X" at 284.607,42.529 h1.52
  text "LIQUID PHOTOIMAGEABLE" at 287.147,42.529 h1.14
  text "SCREEN PRINT" at 326.517,42.529 h1.14
  text "MATTE" at 287.147,39.481 h1.14
  text "GLOSS" at 299.847,39.481 h1.14
  text "GREEN" at 314.198,39.481 h1.14
  text "BLUE" at 326.517,39.481 h1.14
  text "G/Y" at 340.487,39.481 h1.14
  text "OTHER" at 351.917,39.481 h1.14
  text "X" at 297.18,39.354 h1.52
  text "SOLDER MASK COLOUR:" at 261.62,36.56 h1.14
  text "BLACK" at 287.147,36.433 h1.14
  text "GREEN" at 299.847,36.433 h1.14
  text "YELLOW" at 314.198,36.433 h1.14
  text "BLUE" at 326.517,36.433 h1.14
  text "OTHER" at 340.487,36.433 h1.14
  text "X" at 284.48,36.306 h1.52
  text "TRACK FINISH:" at 261.62,33.512 h1.52
  text "SELECTIVE SOLDER (HASL)" at 287.147,33.385 h1.14
  text "REFLOW SOLDER" at 326.517,33.385 h1.14
  text "SELECTIVE GOLD" at 287.147,30.337 h1.14
  text "um  (AREA" at 314.198,30.337 h1.14
  text "sq. mm)" at 342.011,30.337 h1.14
  text "X" at 284.607,27.289 h1.52
  text "IMMERSION GOLD" at 287.147,27.289 h1.14
  text "OTHER" at 326.517,27.289 h1.14
  text "EDGE BOARD" at 261.62,24.368 h1.52
  text "1.3um HARD GOLD OVER 5um     NICKEL / TIN-NICKEL" at 287.147,24.241 h1.14
  text "CONTACTS:" at 261.62,22.209 h1.52
  text "HARD FINISH GOLDE PLATE" at 287.147,21.193 h1.14
  text "OTHER" at 326.517,21.193 h1.14
  text "AS SHOWN" at 287.147,18.145 h1.14
  text "REFER" at 326.517,18.145 h1.14
  text "PROFILING:" at 261.62,15.097 h1.52
  text "AS DIMENSIONED, MEASURED AND CUT FROM SPECIFIED DATUM." at 287.147,15.097 h1.14
  text "X" at 284.607,14.97 h1.52
  text "REFER PCB BLANK DWG No." at 287.274,12.176 h1.27
  text "USE PROFILE / ROUTE TAPE SUPPLIED (REFER PATTERN MASTER LIST)" at 287.274,9.128 h1.27
  text "SQUARE CUT" at 287.274,6.08 h1.27
  text "N.C. ROUTE" at 305.054,6.08 h1.27
  text "V. SCORE" at 322.834,6.08 h1.27
  text "BLANK" at 340.614,6.08 h1.27
  text "ACCEPTABILITY:" at 261.62,3.413 h1.52
  text "MATERIALS AND WORKMANSHIP FOR ALL PRINTED WIRING BOARDS TO MEET" at 283.845,3.286 h1.27
  text "OR EXCEED THE REQUIREMENTS OF:" at 283.845,0.492 h1.27
  text "IPC-6011/12 AND IPC-A-600E" at 287.401,-2.175 h1.27
  text "1" at 322.961,-2.175 h1.27
  text "2" at 331.851,-2.175 h1.27
  text "X" at 329.184,-2.302 h1.52
  text "X" at 284.734,-2.429 h1.52
  text "3" at 340.741,-4.334 h1.27
  text "UL CERTIFICATION" at 287.401,-5.223 h1.27
  text "AUSTEL" at 322.961,-5.223 h1.27
  text "X" at 284.734,-5.35 h1.52
  text "ML-P-55110F GRP" at 286.893,-8.271 h1.02
  text "A" at 305.181,-8.271 h1.27
  text "B" at 314.071,-8.271 h1.27
  text "AS2546" at 322.961,-8.271 h1.27
  text "OTHER" at 340.741,-8.271 h1.27
  text "ADDITIONAL" at 261.62,-11.192 h1.52
  text "NONE" at 287.401,-11.446 h1.27
  text "SAMPLE PLAN" at 305.181,-11.446 h1.27
  text "MIL-P-55110E SERIAL Nos. PER ORDER" at 322.961,-11.446 h1.27
  text "REQUIREMENTS:" at 261.62,-13.605 h1.52
  text "NONE" at 287.401,-14.494 h1.27
  text "ML-P-55110F GRP" at 304.673,-14.494 h1.02
  text "A" at 322.961,-14.494 h1.27
  text "B" at 331.851,-14.494 h1.27
  text "IPC CLASS:" at 337.82,-14.494 h1.27
  text "1" at 353.314,-14.494 h1.27
  text "2" at 359.664,-14.494 h1.27
  text "3" at 366.014,-14.494 h1.27
  text "QUALITY RELEASE REPORT" at 305.181,-17.542 h1.27
  text "OTHER" at 345.694,-17.542 h1.27
  text "PER ORDER" at 354.203,-17.669 h1.27
  text "X" at 343.027,-17.796 h1.52
  text "NONE" at 305.181,-20.59 h1.27
  text "REQUIRED" at 322.961,-20.59 h1.27
  text "PER ORDER" at 345.821,-20.59 h1.27
  text "ELECTRICAL TEST:" at 261.62,-20.717 h1.52
  text "X" at 320.294,-20.717 h1.52
  text "NONE" at 305.181,-23.638 h1.27
  text "1 SIDE" at 322.834,-23.638 h1.14
  text "2 SIDES" at 334.01,-23.638 h1.14
  text "MIN. PITCH" at 345.694,-23.638 h1.27
  text "0.65mm" at 359.283,-23.638 h1.27
  text "SURFACE MOUNT:" at 261.62,-23.765 h1.52
  text "X" at 331.775,-23.841 h1.52
  text "NONE" at 305.181,-26.686 h1.27
  text "FOIL" at 322.961,-26.686 h1.27
  text "LEGEND" at 334.391,-26.686 h1.27
  text "REFER" at 345.694,-26.686 h1.27
  text "MANUFACTURER'S ID/LOGO:" at 261.62,-26.813 h1.52
  text "ISO9001/AS3901" at 308.991,-29.734 h1.27
  text "NONE" at 345.694,-29.734 h1.27
  text "MANUFACTURER'S ACCREDITATION:" at 261.62,-29.861 h1.52
  text "X" at 306.324,-29.861 h1.52
  text "PER ORDER" at 305.181,-32.782 h1.27
  text "REFER" at 322.961,-32.782 h1.27
  text "PACKAGING AND HANDLING:" at 261.62,-32.909 h1.52
  text "X" at 302.514,-33.036 h1.52
Sheet:
  drawing of 1882 lines, arcs and shapes, not listed
  text "1" at 3.717,207.391 h1.78
  text "2" at 52.756,207.391 h1.78
  text "3" at 102.015,207.391 h1.78
  text "4" at 151.308,207.391 h1.78
  text "5" at 200.584,207.391 h1.78
  text "6" at 249.606,207.391 h1.78
  text "7" at 299.136,207.391 h1.78
  text "8" at 348.158,207.391 h1.78
  text "A" at -18.415,173.406 h1.78
  text "A" at 370.205,173.406 h1.78
  text "B" at -18.415,102.794 h1.78
  text "B" at 370.205,102.794 h1.78
  text "C" at -18.415,32.182 h1.78
  text "C" at 370.205,32.182 h1.78
  text "D" at -18.415,-37.922 h1.78
  text "D" at 370.205,-37.922 h1.78
  text "ENGINEER:" at 255.27,-38.1 h1.14
  text "TITLE:" at 293.37,-38.1 h1.14
  text "PCB DESIGNER:" at 255.27,-45.593 h1.14
  text "DATE:" at 255.27,-53.34 h1.14
  text "PART NO.:" at 293.37,-53.34 h1.14
  text "REV:" at 346.71,-53.34 h1.14
  text "Altium Limited" at 222.25,-55.88 h1.78
  text ".PRINT_DATE" at 256.54,-56.388 h1.78
  text "12a Rodborough Rd" at 222.25,-58.42 h1.78
  text "Frenchs Forest" at 222.25,-60.96 h1.78
  text "FILE NAME:" at 255.27,-60.96 h1.14
  text "DWG NO:" at 293.37,-60.96 h1.14
  text "SCALE:" at 346.71,-60.96 h1.14
  text "NSW 2086" at 222.25,-63.5 h1.78
  text ".PCB_FILE_NAME_NO_PATH" at 256.54,-64.008 h1.78
  text "1" at 3.717,-69.469 h1.78
  text "2" at 52.756,-69.469 h1.78
  text "3" at 102.015,-69.469 h1.78
  text "4" at 151.308,-69.469 h1.78
  text "5" at 200.584,-69.469 h1.78
  text "6" at 249.606,-69.469 h1.78
  text "7" at 299.136,-69.469 h1.78
  text "8" at 348.158,-69.469 h1.78
Drill Drawing:
  text ".Legend" at 0,-8 h0.75

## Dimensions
0.001,0.001 to 68.999,0.001 on Dimensions
0.001,0.001 to 0.001,77 on Dimensions
34.5,-69.801 to 34.5,84 on Dimensions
